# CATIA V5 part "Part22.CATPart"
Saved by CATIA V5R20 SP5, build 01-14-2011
Part number: Part22
Material "Water": density 1000 kg/m3
Bounding box of the stored display mesh (mm): x -1.919 to 1.919, y -2 to 2, z -1.919 to 1.919
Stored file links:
  D:\新建文件夹\Part22.CATPart
  C:\Program Files\Dassault Systemes\B20\intel_a\startup\materials\Catalog.CATMaterial
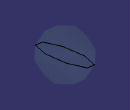
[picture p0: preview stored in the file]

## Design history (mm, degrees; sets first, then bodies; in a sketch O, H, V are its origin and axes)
Body1 (main body), material "Water"
  Sketch1 on xy-plane, origin (0, 0, 0), H (1, 0, 0), V (0, 1, 0)
    arc A1 centre (0, 0) radius 2 from (0, -2) to (0, 2) ccw
    axis line L1 (0, 5.9256) -> (0, -6.5373)
    point P1 (0, 5.9256)
    point P3 (0, 2)
    point P4 (0, -2)
    radius A1 = 2
    coincidence: P1 V, L1 P3, L1 P4
    vertical: L1 V
  Shaft1: profile Sketch1, axis Sketch1.L1, angle 360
